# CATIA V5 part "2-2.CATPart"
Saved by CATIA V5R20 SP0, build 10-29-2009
Part number: 2-2
Material "Steel": density 7860 kg/m3, Young's modulus 2e+11 Pa, Poisson ratio 0.266, thermal expansion 1.17e-05 1/K
Bounding box of the stored display mesh (mm): x -1 to 1, y -16 to 16, z -47.99 to 1
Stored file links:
  E:\Ehsan\Amoozesh\CATIA\CATIA Course\Advanced\Videos\Session-17\2-2.CATPart
  D:\CATIA V5R20\B20\intel_a\startup\materials\Catalog.CATMaterial
  E:\Ehsan\Amoozesh\CATIA\CATIA Course\Advanced\Videos\Session-17\Product1.CATProduct
  D:\CATIA V5R20\B20\intel_a\resources\graphic\figures\CATIA_EnvironmentMap_Satin_512x512.jpg
  D:\CATIA V5R20\B20\intel_a\resources\graphic\figures\CATIA_EnvironmentMap_NonLinear_512x512.jpg
  D:\CATIA V5R20\B20\intel_a\resources\graphic\figures\CATIA_EnvironmentMap_YellowSatin_512x512.jpg
  D:\CATIA V5R20\B20\intel_a\resources\graphic\figures\CATIA_EnvironmentMap_Grey_512x512.jpg
  D:\CATIA V5R20\B20\intel_a\resources\graphic\figures\CATIA_EnvironmentMap_DSBlack_512x512.jpg
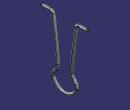
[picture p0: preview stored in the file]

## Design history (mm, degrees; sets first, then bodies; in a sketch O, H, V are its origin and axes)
AxisSystem1: origin (0, 0, 0), X (1, 0, 0), Y (0, 1, 0), Z (0, 0, 1)
Set1
  Plane1: type Normal, Curve Sketch1, RefPoint Sketch1.P16
Body1 (main body), material "Steel"
  Sketch1 on YZ plane of AxisSystem1, origin (0, 0, 0), H (0, 1, 0), V (0, 0, 1)
    point P1 (-16, 0)
    line L1 (-16, 0) -> (-10.4, 0)
    point P2 (-10.4, 0)
    arc A1 centre (-10.4, -2) radius 2 from (-10.4, 0) to (-8.4267, -1.674) cw
    point P4 (-8.4267, -1.674)
    arc A2 centre (-304.4148, -50.5729) radius 300 from (-8.4267, -1.674) to (-5.0099, -31.6852) cw
    point P6 (-5.0099, -31.6852)
    arc A3 centre (-10, -32) radius 5 from (-5.0099, -31.6852) to (-5.9768, -34.9689) cw
    point P7 (-10, -32)
    point P8 (-5.9768, -34.9689)
    line L2 (-5.9768, -34.9689) -> (-8.1639, -37.9326)
    point P9 (-8.1639, -37.9326)
    arc A4 centre (-5.75, -39.7139) radius 3 from (-8.1639, -37.9326) to (-8.625, -40.5709) ccw
    point P11 (-8.625, -40.5709)
    arc A5 centre (0, -38) radius 9 from (-8.625, -40.5709) to (8.625, -40.5709) ccw
    reference projected line E1 through (0, 0) direction (0, 1) from edge [ZX plane of AxisSystem1 | YZ plane of AxisSystem1]
    point P15 (10.4, 0)
    point P16 (16, 0)
    line L3 (16, 0) -> (10.4, 0)
    point P17 (8.4267, -1.674)
    arc A6 centre (10.4, -2) radius 2 from (10.4, 0) to (8.4267, -1.674) ccw
    point P19 (5.0099, -31.6852)
    arc A7 centre (304.4148, -50.5729) radius 300 from (8.4267, -1.674) to (5.0099, -31.6852) ccw
    point P21 (5.9768, -34.9689)
    arc A8 centre (10, -32) radius 5 from (5.0099, -31.6852) to (5.9768, -34.9689) ccw
    point P23 (8.1639, -37.9326)
    line L4 (5.9768, -34.9689) -> (8.1639, -37.9326)
    point P24 (8.625, -40.5709)
    arc A9 centre (5.75, -39.7139) radius 3 from (8.1639, -37.9326) to (8.625, -40.5709) cw
    distance P16 P1 = 32
    radius A3 = 5
    radius A4 = 3
    distance H A5 = 47
    radius A5 = 9
    distance A9 A4 = 17.5
    distance P7 A5 V = 15
    radius A2 = 300
    distance A3 A8 = 10
    distance A6 A1 = 16.8
    radius A6 = 2
    coincidence: P1 H
    horizontal: L1 H
    tangency: A1 L1, A2 A1, A3 A2, L2 A3, A4 L2, A5 A4, A5 A9
    symmetry: P2 P15 E1, P1 P16 E1, L1 L3 E1, P4 P17 E1, A1 A6 E1, P6 P19 E1, A2 A7 E1, P8 P21 E1, A3 A8 E1, P9 P23 E1, L2 L4 E1, P11 P24 E1, A4 A9 E1
  Sketch2 on Plane1, origin (0, 16, 0), H (-1, 0, 0), V (0, 0, 1)
    circle A1 centre (0, 0) radius 1
    radius A1 = 1
  Rib1: profile Sketch2, centre curve Sketch1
